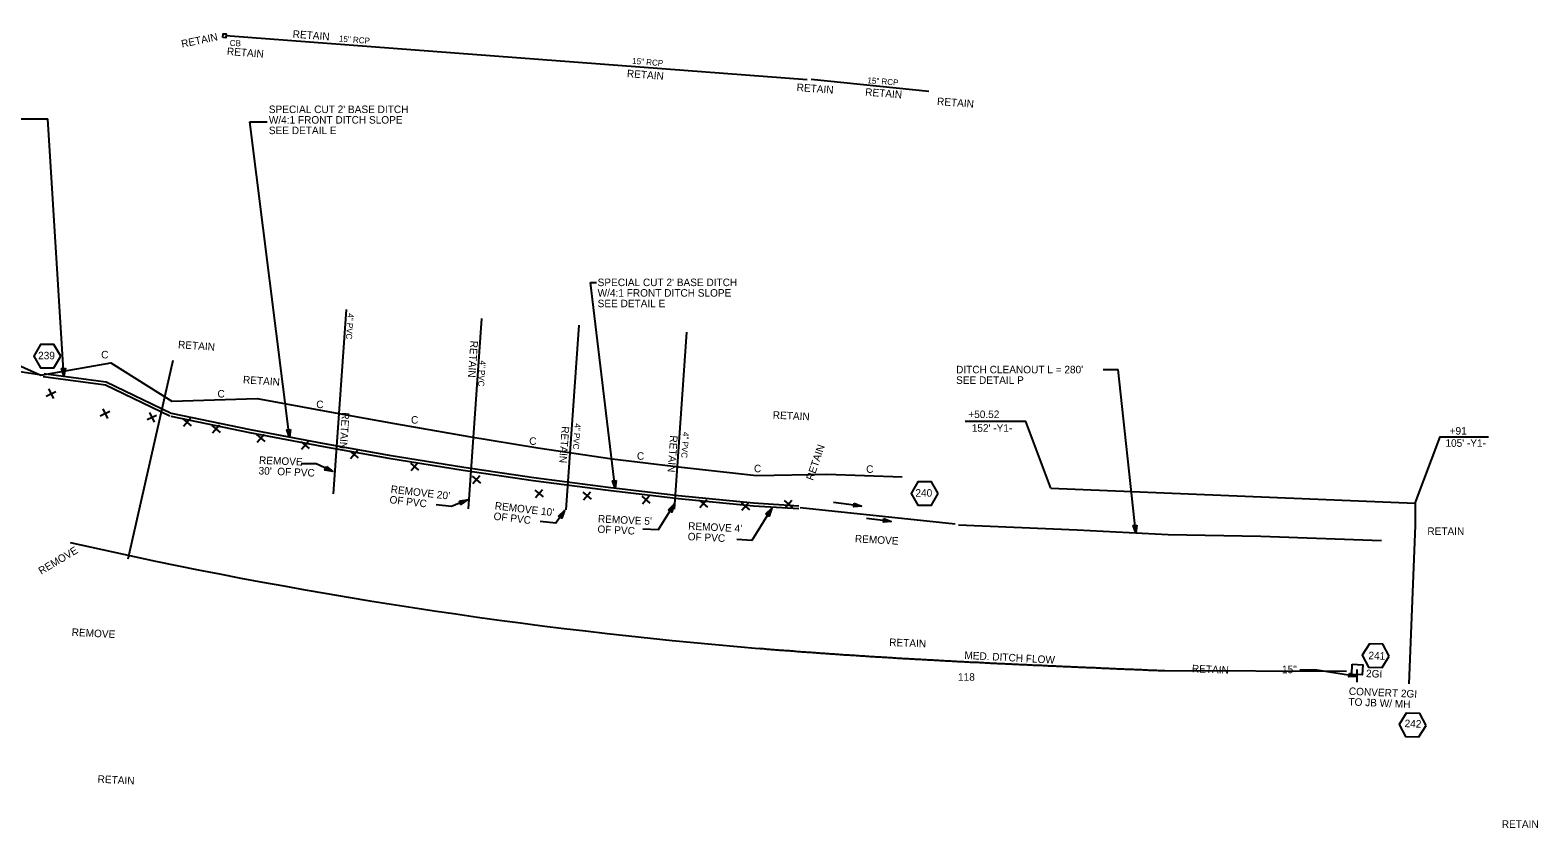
# Model space of a CAD drawing. Extents: x 2384780 to 2405432, y 547869 to 573706.
# Drawn here: x 2399052 to 2400053, y 552310 to 552840 of the extents above; entities that cross this region are included whole.
import ezdxf

# ---------------------------------------------------------------- set-up
doc = ezdxf.new("R2010")
doc.units = 0
for name, color, linetype in [('Old_Level_1', 7, 'Continuous'), ('Old_Level_18', 7, 'Continuous'), ('Old_Level_19', 7, 'Continuous'), ('Old_Level_23', 7, 'Continuous'), ('Old_Level_5', 7, 'Continuous'), ('Old_Level_58', 7, 'Continuous'), ('Old_Level_63', 7, 'Continuous'), ('Old_Level_9', 7, 'Continuous'), ('Prop Drainage Box Number Symbol CELL', 7, 'Continuous')]:
    doc.layers.add(name, color=color, linetype=linetype)

# ---------------------------------------------------------------- blocks, each defined once
blk = doc.blocks.new('SPOT')
at = {"layer": 'Old_Level_1'}
for p, q in [((-5.48625, 4.61225), (5.48625, -4.61175)), ((-4.608, -5.326), (4.609, 5.325))]:
    blk.add_line(p, q, dxfattribs=at)
blk = doc.blocks.new('AH1')
at = {"layer": 'Old_Level_23'}
blk.add_lwpolyline([(-5.28, 1.32), (0, 0), (-5.28, -1.32)], close=True, dxfattribs=at)
blk = doc.blocks.new('IN')
at = {"layer": 'Old_Level_9'}
blk.add_lwpolyline([(-0.07025, 0.067), (0.07025, 0.067), (0.07025, -0.067), (-0.07025, -0.067)], close=True, dxfattribs=at)

msp = doc.modelspace()

# ---------------------------------------------------------------- linework, layer by layer
at = {"layer": 'Old_Level_1'}
for p, q in [((2398995.1, 552620.8), (2399059.1, 552610.8)), ((2399562.7, 552522.6), (2399665.6, 552511.8)), ((2399932.5, 552406.7), (2399932.6, 552415.1))]:
    msp.add_line(p, q, dxfattribs=at)
for points in [[(2399252.5, 552546.5), (2399241.4, 552551.7), (2399231.4, 552551.8)], [(2399341.9, 552527.9), (2399331.3, 552523.3), (2399321, 552524.5)], [(2399406.2, 552520.7), (2399400.5, 552512.3), (2399390.1, 552513.5)], [(2399479.2, 552524.9), (2399468.4, 552507.9), (2399458.4, 552508.4)], [(2399543.9, 552522.2), (2399530.7, 552500.9), (2399520.8, 552501.4)]]:
    msp.add_lwpolyline(points, dxfattribs=at)
for points in [[(2399953.9, 552424), (2399949.7, 552431.9), (2399940.8, 552432.2), (2399936, 552424.6), (2399940.2, 552416.7), (2399949.1, 552416.4)], [(2399978.3, 552377.9), (2399974.1, 552385.9), (2399965.2, 552386.2), (2399960.4, 552378.6), (2399964.6, 552370.7), (2399973.5, 552370.4)]]:
    msp.add_lwpolyline(points, close=True, dxfattribs=at)
at = {"layer": 'Old_Level_18'}
for points in [[(2399060.8, 552611.6), (2399063.7, 552611.2), (2399102.1, 552606.1), (2399145.1, 552585.4)], [(2399060.2, 552609.7), (2399063.4, 552609.2), (2399101.5, 552604.2), (2399144.2, 552583.6)], [(2399145, 552583.4), (2399197.2, 552572.5), (2399246.3, 552563.1), (2399289.7, 552555.4), (2399339, 552547.5), (2399385.6, 552540.7), (2399435.2, 552534.2), (2399481.9, 552528.7), (2399531.7, 552523.8), (2399562, 552522)], [(2399145.1, 552585.4), (2399197.6, 552574.5), (2399246.8, 552565.1), (2399290, 552557.4), (2399339.4, 552549.4), (2399385.9, 552542.6), (2399435.4, 552536.2), (2399482.1, 552530.7), (2399531.9, 552525.7), (2399561.9, 552523.9)], [(2399667.9, 552511.1), (2399746.6, 552507.8), (2399807.1, 552504.7), (2399868.6, 552503.6), (2399948.7, 552500.9)]]:
    msp.add_lwpolyline(points, dxfattribs=at)
at = {"layer": 'Old_Level_19'}
msp.add_line((2399804.9, 552414.4), (2399925.5, 552414), dxfattribs=at)
msp.add_arc((2399806.6, 555716), 3298, 257.2394, 265.2838, dxfattribs=at)
msp.add_spline([(2399535.4, 552429.2), (2399539, 552428.9), (2399542.7, 552428.6), (2399546.3, 552428.3), (2399550, 552428), (2399553.6, 552427.8), (2399557.2, 552427.5), (2399560.9, 552427.2), (2399564.5, 552426.9), (2399568.1, 552426.7), (2399571.8, 552426.4), (2399575.4, 552426.1), (2399579, 552425.9), (2399582.7, 552425.6), (2399586.3, 552425.4), (2399590, 552425.1), (2399593.6, 552424.9), (2399597.2, 552424.7), (2399600.9, 552424.4), (2399604.5, 552424.2), (2399608.2, 552423.9), (2399611.8, 552423.7), (2399615.4, 552423.5), (2399619.1, 552423.3), (2399622.7, 552423.1), (2399626.4, 552422.8), (2399630, 552422.6), (2399633.6, 552422.4), (2399637.3, 552422.2), (2399640.9, 552422), (2399644.6, 552421.8), (2399648.2, 552421.6), (2399651.8, 552421.4), (2399655.5, 552421.2), (2399659.1, 552421), (2399662.8, 552420.8), (2399666.4, 552420.6), (2399670.1, 552420.4), (2399673.7, 552420.2), (2399677.3, 552420), (2399681, 552419.9), (2399684.6, 552419.7), (2399688.3, 552419.5), (2399691.9, 552419.3), (2399695.6, 552419.1), (2399699.2, 552419), (2399702.8, 552418.8), (2399706.5, 552418.6), (2399710.1, 552418.5), (2399713.8, 552418.3), (2399717.4, 552418.1), (2399721.1, 552418), (2399724.7, 552417.8), (2399728.4, 552417.6), (2399732, 552417.5), (2399735.6, 552417.3), (2399739.3, 552417.1), (2399742.9, 552417), (2399746.6, 552416.8), (2399750.2, 552416.7), (2399753.9, 552416.5), (2399757.5, 552416.4), (2399761.2, 552416.2), (2399764.8, 552416), (2399768.4, 552415.9), (2399772.1, 552415.7), (2399775.7, 552415.6), (2399779.4, 552415.4), (2399783, 552415.3), (2399786.7, 552415.1), (2399790.3, 552415), (2399794, 552414.8), (2399797.6, 552414.7), (2399801.3, 552414.5), (2399804.9, 552414.4)], degree=3, dxfattribs=at)
at = {"layer": 'Old_Level_5'}
for p, q in [((2399024, 552780.7), (2399063.2, 552780.7)), ((2399073.9, 552610.2), (2399063.2, 552780.7)), ((2399223.8, 552569.5), (2399197.4, 552778.7)), ((2399197.4, 552778.7), (2399208.8, 552778.7)), ((2399440, 552535.6), (2399423.6, 552672.1)), ((2399423.6, 552672.1), (2399427.5, 552672.1)), ((2399764, 552614.3), (2399774, 552614.3)), ((2399785.7, 552505.8), (2399774, 552614.3)), ((2399603.4, 552523.7), (2399584.8, 552526.1)), ((2399623.2, 552513.5), (2399606.8, 552515.4)), ((2399894.5, 552415), (2399904.5, 552415)), ((2399932.3, 552410.6), (2399904.5, 552415))]:
    msp.add_line(p, q, dxfattribs=at)
for points in [[(2399074.9, 552615.3), (2399073.9, 552610.2), (2399072.4, 552615.1)], [(2399224.4, 552574.6), (2399223.8, 552569.5), (2399221.9, 552574.3)], [(2399440.7, 552540.7), (2399440, 552535.6), (2399438.2, 552540.4)], [(2399598.6, 552525.6), (2399603.4, 552523.7), (2399598.3, 552523.1)], [(2399618.4, 552515.4), (2399623.2, 552513.5), (2399618.1, 552512.9)], [(2399786.4, 552510.9), (2399785.7, 552505.8), (2399783.9, 552510.7)], [(2399927.5, 552412.6), (2399932.3, 552410.6), (2399927.1, 552410.2)]]:
    msp.add_lwpolyline(points, close=True, dxfattribs=at)
at = {"layer": 'Old_Level_58'}
for p, q in [((2399261.4, 552654.1), (2399252.8, 552531.7)), ((2399351.3, 552648.2), (2399342.4, 552521.9)), ((2399415.9, 552643.7), (2399407.3, 552521.1)), ((2399487.4, 552639.2), (2399479.2, 552521.5))]:
    msp.add_line(p, q, dxfattribs=at)
msp.add_lwpolyline([(2399179.5, 552834.7), (2399179.6, 552837.2), (2399181.6, 552837.2), (2399181.5, 552834.6)], close=True, dxfattribs=at)
for points in [[(2399567.4, 552806.6), (2399181.5, 552835.9)], [(2399648.3, 552799), (2399570.1, 552806.9)]]:
    msp.add_lwpolyline(points, dxfattribs=at)
at = {"layer": 'Old_Level_63'}
for p, q in [((2399116.7, 552488.7), (2399146.5, 552620.6)), ((2399729.1, 552535.6), (2399971.1, 552525.6)), ((2399971.1, 552525.6), (2399971.1, 552510.7)), ((2399971.1, 552510.7), (2399966.8, 552405.7))]:
    msp.add_line(p, q, dxfattribs=at)
for points in [[(2398915, 552653.9), (2398961.5, 552634.8), (2399012.5, 552631.2), (2399058.6, 552610.5), (2399105.1, 552618.8), (2399145.6, 552593.3)], [(2399145.6, 552593.3), (2399202.3, 552595), (2399251.5, 552586.1), (2399293.4, 552578.4), (2399342.7, 552569.8), (2399388.5, 552562.4), (2399438, 552555.1), (2399484, 552549.5), (2399533.8, 552544), (2399580.5, 552544.8), (2399630.5, 552543.1)], [(2399729.1, 552535.6), (2399712.6, 552579.7), (2399672.3, 552579.7)], [(2399971.1, 552525.6), (2399987.6, 552569.7), (2400019.9, 552569.7)]]:
    msp.add_lwpolyline(points, dxfattribs=at)
at = {"layer": 'Prop Drainage Box Number Symbol CELL'}
for points in [[(2399071.8, 552623.2), (2399067.3, 552630.9), (2399058.3, 552630.9), (2399053.9, 552623.2), (2399058.3, 552615.4), (2399067.3, 552615.4)], [(2399654.4, 552532), (2399649.9, 552539.7), (2399640.9, 552539.7), (2399636.5, 552532), (2399640.9, 552524.2), (2399649.9, 552524.2)]]:
    msp.add_lwpolyline(points, close=True, dxfattribs=at)

# ---------------------------------------------------------------- block references
at = {"layer": 'Old_Level_23'}
for p, xscale, yscale, rotation in [((2399252.5, 552546.5), 1.0000041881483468, 1.0000041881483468, -24.749201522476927), ((2399341.9, 552527.9), 0.999997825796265, 0.9999978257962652, 22.666637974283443), ((2399406.2, 552520.7), 0.9999994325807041, 0.9999994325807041, 58.313772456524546), ((2399479.2, 552524.9), 0.9999994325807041, 0.9999994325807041, 58.313772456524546), ((2399543.9, 552522.2), 0.9999994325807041, 0.9999994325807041, 58.313772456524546)]:
    msp.add_blockref('AH1', p, dxfattribs=dict(at, xscale=xscale, yscale=yscale, rotation=rotation))
at = {"layer": 'Old_Level_5', "xscale": 50.00000000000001, "yscale": 50.000000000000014, "rotation": -2.443099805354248}
msp.add_blockref('IN', (2399932.6, 552415.1), dxfattribs=at)
at = {"layer": 'Old_Level_63', "xscale": 0.5, "yscale": 0.5, "rotation": -23.707700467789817}
for p in [(2399065.4, 552598.2), (2399101.3, 552585.1), (2399132.3, 552582.6)]:
    msp.add_blockref('SPOT', p, dxfattribs=at)
at = {"layer": 'Old_Level_63', "xscale": 0.5, "yscale": 0.5}
for p in [(2399155.6, 552579.3), (2399175, 552574.9), (2399204.6, 552568.8), (2399234.1, 552564.1), (2399266.5, 552557.9), (2399306.7, 552549.9), (2399347.7, 552541.2), (2399389.3, 552532), (2399421.2, 552530.5), (2399460.3, 552527.9), (2399498.5, 552525.3), (2399526.3, 552523.5), (2399554.9, 552525)]:
    msp.add_blockref('SPOT', p, dxfattribs=at)

# ---------------------------------------------------------------- texts
at = {"layer": 'Old_Level_1'}
for s, rotation, p in [('RETAIN', 11.6778, (2399152.4, 552828)), ('RETAIN', 355.7147, (2399225.7, 552834.7)), ('RETAIN', 355.7147, (2399182, 552823.2)), ('RETAIN', 355.7147, (2399447.6, 552808.5)), ('RETAIN', 355.7147, (2399560.3, 552799.3)), ('RETAIN', 355.7147, (2399605.8, 552796.2)), ('RETAIN', 355.7147, (2399653.5, 552790)), ('RETAIN', 356.037, (2399149.6, 552628.5)), ('RETAIN', 265.9845, (2399343.9, 552633.6)), ('RETAIN', 356.037, (2399192.7, 552605.2)), ('RETAIN', 265.9845, (2399258.6, 552586.1)), ('RETAIN', 357.3077, (2399544.5, 552581.7)), ('RETAIN', 265.9845, (2399404.5, 552576.8)), ('RETAIN', 265.9845, (2399476.5, 552570.7)), ('RETAIN', 71.2006, (2399571.3, 552540.3)), ('REMOVE', 357.7004, (2399203.4, 552551.7)), ("30'  OF PVC", 357.7004, (2399203.1, 552544.7)), ('OF PVC', 353.3341, (2399289.9, 552525.6)), ("REMOVE 20'", 353.3341, (2399290.7, 552532.5)), ("REMOVE 10'", 353.3341, (2399359.8, 552521.5)), ('OF PVC', 353.3341, (2399359, 552514.6)), ('OF PVC', 357.2328, (2399428.1, 552505.9)), ("REMOVE 5'", 357.2328, (2399428.4, 552512.8)), ("REMOVE 4'", 357.2328, (2399488.3, 552508)), ('OF PVC', 357.2328, (2399488, 552501)), ('REMOVE', 356.8036, (2399599, 552499.6)), ('REMOVE', 30.9097, (2399058.9, 552478)), ('REMOVE', 357.0476, (2399079, 552437.5)), ('RETAIN', 357.5569, (2399621.8, 552430.8)), ('241', 357.8481, (2399940, 552422)), ('RETAIN', 357.5569, (2399822.8, 552413.3)), ('2GI', 357.5569, (2399938.4, 552410.1)), ('CONVERT 2GI', 357.5569, (2399927, 552398.3)), ('TO JB W/ MH', 357.5569, (2399926.7, 552391.3)), ('242', 357.8481, (2399964, 552376.9)), ('RETAIN', 357.1511, (2399096.2, 552340))]:
    msp.add_text(s, height=5, rotation=rotation, dxfattribs=at).set_placement(p)
at = {"layer": 'Old_Level_19'}
msp.add_text('MED. DITCH FLOW', height=5, rotation=356.9584, dxfattribs=at).set_placement((2399671.7, 552422.2))
msp.add_text('118', height=5, dxfattribs=at).set_placement((2399667.6, 552407.7))
at = {"layer": 'Old_Level_5'}
for s, p in [('W/4:1 FRONT DITCH SLOPE ', (2399210, 552777.6)), ("SPECIAL CUT 2' BASE DITCH", (2399210, 552784.6)), ('SEE DETAIL E', (2399210, 552770.6)), ("SPECIAL CUT 2' BASE DITCH", (2399428.3, 552669.7)), ('W/4:1 FRONT DITCH SLOPE ', (2399428.3, 552662.7)), ('SEE DETAIL E', (2399428.3, 552655.7)), ('SEE DETAIL P', (2399666.3, 552604.8)), ("DITCH CLEANOUT L = 280'", (2399666.3, 552611.8)), ('RETAIN', (2399979.2, 552504.5)), ('15"', (2399882.7, 552412.7)), ('RETAIN', (2400028.6, 552310))]:
    msp.add_text(s, height=5, dxfattribs=at).set_placement(p)
at = {"layer": 'Old_Level_58'}
for s, rotation, p in [('CB', 358.0094, (2399184, 552829.2)), ('15" RCP', 355.5985, (2399256.4, 552832.1)), ('15" RCP', 355.5985, (2399451.1, 552817.3)), ('15" RCP', 355.5985, (2399607.3, 552804.4)), ('4" PVC', 265.9845, (2399262.4, 552651.8)), ('4" PVC', 265.9845, (2399350.1, 552620.5)), ('4" PVC', 265.9845, (2399413.1, 552578.7)), ('4" PVC', 265.9845, (2399485, 552573))]:
    msp.add_text(s, height=4, rotation=rotation, dxfattribs=at).set_placement(p)
at = {"layer": 'Old_Level_63'}
for s, p in [('C', (2399098.7, 552621.7)), ('C', (2399175.9, 552595.7)), ('C', (2399241.5, 552588.7)), ('C', (2399304.4, 552578.4)), ('+50.52', (2399674.4, 552582.1)), ("152' -Y1-", (2399676.7, 552573)), ('+91', (2399994, 552571.1)), ('C', (2399382.9, 552564.3)), ("105' -Y1-", (2399991.2, 552563)), ('C', (2399454.4, 552554.4)), ('C', (2399532.1, 552546.1)), ('C', (2399606.6, 552545.7))]:
    msp.add_text(s, height=5, dxfattribs=at).set_placement(p)
at = {"layer": 'Prop Drainage Box Number Symbol CELL'}
for s, p in [('239', (2399056.8, 552621.1)), ('240', (2399639.3, 552529.9))]:
    msp.add_text(s, height=5, dxfattribs=at).set_placement(p)

doc.saveas('drawing.dxf')
